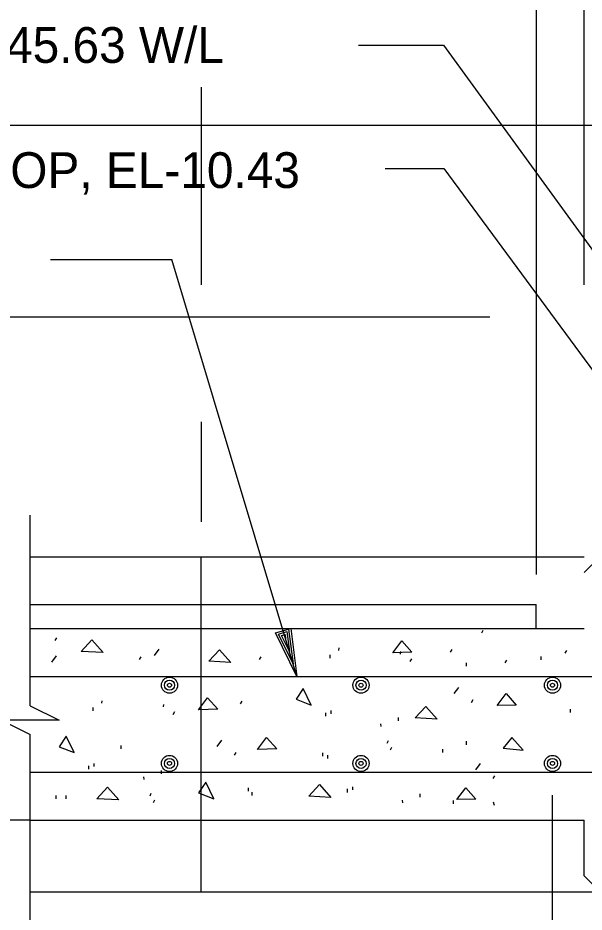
# Model space of a CAD drawing. Extents: x 22369.6 to 22428.3, y 22369.6 to 22415.
# Drawn here: x 22398.083 to 22401.04, y 22382.151 to 22386.818 of the extents above; entities that cross this region are included whole.
import ezdxf

# ---------------------------------------------------------------- set-up
doc = ezdxf.new("R2010")
doc.units = 0
for name, color, linetype in [('Level 1', 7, 'Continuous'), ('Level 10', 7, 'Continuous'), ('Level 2', 7, 'Continuous'), ('Level 4', 7, 'Continuous'), ('Level 44', 7, 'Continuous'), ('Level 7', 7, 'Continuous')]:
    doc.layers.add(name, color=color, linetype=linetype)

msp = doc.modelspace()

# ---------------------------------------------------------------- linework, layer by layer
at = {"layer": 'Level 1'}
for p, q in [((22401.0396, 22385.4259), (22401.0396, 22388.9181)), ((22400.7896, 22387.1129), (22400.7896, 22383.9134)), ((22399.0396, 22386.4577), (22399.0396, 22385.426)), ((22402.0747, 22386.2564), (22394.9397, 22386.2564)), ((22398.2527, 22385.5571), (22398.8874, 22385.5571)), ((22399.5394, 22383.3813), (22398.8874, 22385.5571)), ((22400.5471, 22385.2563), (22395.7532, 22385.2563)), ((22399.0396, 22384.7106), (22399.0396, 22384.1879)), ((22398.1476, 22383.2277), (22398.1476, 22384.2231)), ((22398.1476, 22381.9986), (22398.1476, 22383.0782)), ((22400.8745, 22381.0005), (22400.8745, 22382.7621)), ((22398.1476, 22382.6313), (22397.3022, 22382.6313))]:
    msp.add_line(p, q, dxfattribs=at)
for points in [[(22399.8614, 22386.6769), (22400.305, 22386.6769), (22402.2173, 22384.0484)], [(22400.0013, 22386.0316), (22400.3078, 22386.0316), (22401.5475, 22384.3508)], [(22398.1476, 22383.2277), (22398.2976, 22383.1532), (22397.9979, 22383.1532), (22398.1476, 22383.0782)]]:
    msp.add_lwpolyline(points, dxfattribs=at)
at = {"layer": 'Level 10'}
for p, q in [((22398.1476, 22383.3813), (22402.0276, 22383.3813)), ((22398.1476, 22382.8813), (22402.0276, 22382.8813))]:
    msp.add_line(p, q, dxfattribs=at)
for centre, radius in [((22398.8745, 22383.3355), 0.0422), ((22398.8745, 22383.3355), 0.0264), ((22398.8745, 22383.3355), 0.0105), ((22399.8745, 22383.3355), 0.0422), ((22399.8745, 22383.3355), 0.0264), ((22399.8745, 22383.3355), 0.0105), ((22400.8745, 22383.3355), 0.0422), ((22400.8745, 22383.3355), 0.0264), ((22400.8745, 22383.3355), 0.0105), ((22398.8745, 22382.9272), 0.0422), ((22399.8745, 22382.9272), 0.0422), ((22400.8745, 22382.9272), 0.0422), ((22398.8745, 22382.9272), 0.0264), ((22398.8745, 22382.9272), 0.0105), ((22399.8745, 22382.9272), 0.0264), ((22399.8745, 22382.9272), 0.0105), ((22400.8745, 22382.9272), 0.0264), ((22400.8745, 22382.9272), 0.0105)]:
    msp.add_circle(centre, radius, dxfattribs=at)
at = {"layer": 'Level 2'}
for p, q in [((22399.5195, 22383.4477), (22399.5195, 22383.4477)), ((22399.5394, 22383.3813), (22399.5394, 22383.3813))]:
    msp.add_line(p, q, dxfattribs=at)
msp.add_lwpolyline([(22399.5074, 22383.632), (22399.5394, 22383.3813), (22399.4282, 22383.6083), (22399.4959, 22383.6286), (22399.5195, 22383.4477), (22399.444, 22383.6019), (22399.4875, 22383.6149), (22399.5003, 22383.5116), (22399.4599, 22383.5955), (22399.4777, 22383.6009), (22399.4804, 22383.578)], dxfattribs=at)
at = {"layer": 'Level 4'}
for p in [(22398.1476, 22383.7563), (22400.7896, 22383.6313)]:
    msp.add_line(p, (22400.7896, 22383.7563), dxfattribs=at)
at = {"layer": 'Level 44'}
for p, q in [((22400.506, 22383.6087), (22400.5124, 22383.6225)), ((22398.2777, 22383.5686), (22398.2865, 22383.5832)), ((22399.759, 22383.5173), (22399.7602, 22383.5301)), ((22400.3421, 22383.5081), (22400.3509, 22383.5226)), ((22398.7176, 22383.4695), (22398.7263, 22383.4841)), ((22399.3451, 22383.4695), (22399.3539, 22383.4841)), ((22399.7129, 22383.4769), (22399.7129, 22383.4944)), ((22400.0807, 22383.4976), (22400.083, 22383.5107)), ((22400.1315, 22383.459), (22400.1402, 22383.4735)), ((22400.8154, 22383.4672), (22400.8154, 22383.4847)), ((22400.9403, 22383.5026), (22400.9491, 22383.5171)), ((22400.4261, 22383.434), (22400.4261, 22383.4515)), ((22400.6265, 22383.4514), (22400.6352, 22383.466)), ((22398.5211, 22383.2416), (22398.5222, 22383.2544)), ((22399.2454, 22383.2383), (22399.2542, 22383.2529)), ((22400.4523, 22383.2455), (22400.461, 22383.2601)), ((22398.475, 22383.2012), (22398.475, 22383.2187)), ((22398.8427, 22383.2219), (22398.8451, 22383.235)), ((22398.8935, 22383.1833), (22398.9023, 22383.1979)), ((22399.719, 22383.1867), (22399.719, 22383.203)), ((22400.9689, 22383.1936), (22400.9689, 22383.2111)), ((22399.6905, 22383.1735), (22399.6905, 22383.191)), ((22400.0699, 22383.1491), (22400.0699, 22383.1666)), ((22399.9798, 22383.1192), (22399.9787, 22383.1335)), ((22398.6213, 22383.0029), (22398.6213, 22383.0204)), ((22400.011, 22383.0333), (22400.0174, 22383.047)), ((22400.0291, 22382.9985), (22400.0355, 22383.0122)), ((22400.4261, 22383.025), (22400.4261, 22383.0425)), ((22399.2143, 22382.9698), (22399.2231, 22382.9844)), ((22399.6757, 22382.9642), (22399.6757, 22382.9817)), ((22399.7013, 22382.9531), (22399.7013, 22382.9706)), ((22400.301, 22382.9835), (22400.301, 22383.001)), ((22398.4525, 22382.8978), (22398.4525, 22382.9153)), ((22398.4811, 22382.911), (22398.4811, 22382.9273)), ((22398.832, 22382.8734), (22398.832, 22382.8909)), ((22398.7419, 22382.8435), (22398.7407, 22382.8578)), ((22400.5654, 22382.8482), (22400.5742, 22382.8628)), ((22399.2864, 22382.7818), (22399.2864, 22382.7993)), ((22399.3063, 22382.7597), (22399.3063, 22382.7772)), ((22399.8036, 22382.7762), (22399.8036, 22382.7937)), ((22399.8322, 22382.7895), (22399.8322, 22382.8058)), ((22398.2831, 22382.7431), (22398.2831, 22382.7606)), ((22398.3343, 22382.7431), (22398.3343, 22382.7606)), ((22398.7731, 22382.7576), (22398.7795, 22382.7713)), ((22398.7912, 22382.7228), (22398.7976, 22382.7365)), ((22400.093, 22382.7219), (22400.0918, 22382.7362)), ((22400.1831, 22382.7518), (22400.1831, 22382.7693)), ((22400.3578, 22382.7154), (22400.3578, 22382.7329)), ((22400.5722, 22382.7073), (22400.5672, 22382.7248))]:
    msp.add_line(p, q, dxfattribs=at)
for points in [[(22398.413, 22383.5122), (22398.4684, 22383.5723), (22398.5279, 22383.5058)], [(22400.0399, 22383.505), (22400.0869, 22383.5672), (22400.1397, 22383.5074)], [(22399.0796, 22383.4601), (22399.135, 22383.5202), (22399.1945, 22383.4537)], [(22399.5354, 22383.2626), (22399.615, 22383.2316), (22399.573, 22383.3177)], [(22400.5854, 22383.2293), (22400.6324, 22383.2914), (22400.6852, 22383.2316)], [(22399.0262, 22383.2073), (22399.0732, 22383.2694), (22399.126, 22383.2096)], [(22400.1569, 22383.165), (22400.2123, 22383.225), (22400.2718, 22383.1585)], [(22398.2974, 22383.0144), (22398.377, 22382.9835), (22398.335, 22383.0695)], [(22399.3347, 22383.0004), (22399.3817, 22383.0625), (22399.4345, 22383.0027)], [(22400.7205, 22382.9957), (22400.6628, 22383.0622), (22400.6164, 22383.007)], [(22399.0266, 22382.7739), (22399.1062, 22382.743), (22399.0642, 22382.8291)], [(22398.4955, 22382.7428), (22398.5509, 22382.8029), (22398.6104, 22382.7364)], [(22399.6024, 22382.7566), (22399.6578, 22382.8166), (22399.7173, 22382.7501)], [(22400.3741, 22382.7382), (22400.4211, 22382.8003), (22400.4739, 22382.7405)]]:
    msp.add_lwpolyline(points, close=True, dxfattribs=at)
for points in [[(22398.7954, 22383.4905), (22398.8198, 22383.5229)], [(22398.2597, 22383.4557), (22398.2842, 22383.4881)], [(22400.3607, 22383.2916), (22400.3852, 22383.3239)], [(22399.1227, 22383.0159), (22399.1472, 22383.0482)], [(22400.4738, 22382.8943), (22400.4983, 22382.9267)]]:
    msp.add_lwpolyline(points, dxfattribs=at)
at = {"layer": 'Level 7'}
for p, q in [((22398.1476, 22384.0063), (22401.0396, 22384.0063)), ((22399.0396, 22382.2563), (22399.0396, 22384.0063)), ((22401.0396, 22383.923), (22401.123, 22384.0063)), ((22398.1476, 22383.6313), (22401.0396, 22383.6313)), ((22398.1476, 22382.6313), (22401.0396, 22382.6313)), ((22401.0396, 22382.3397), (22401.0396, 22382.6313)), ((22401.123, 22382.2563), (22401.0396, 22382.3397)), ((22398.1476, 22382.2563), (22401.748, 22382.2563))]:
    msp.add_line(p, q, dxfattribs=at)

# ---------------------------------------------------------------- texts
at = {"layer": 'Level 4'}
for s, p in [('STA. 2+45.63 W/L', (22397.1121, 22386.5837)), ('TOP, EL-10.43', (22397.8905, 22385.9306))]:
    msp.add_text(s, height=0.186667, dxfattribs=at).set_placement(p)

doc.saveas('drawing.dxf')
